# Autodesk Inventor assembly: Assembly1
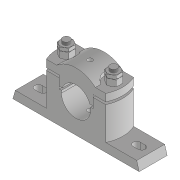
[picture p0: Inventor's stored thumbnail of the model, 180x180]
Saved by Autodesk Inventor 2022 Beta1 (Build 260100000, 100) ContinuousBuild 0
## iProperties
Created: 2021-03
Part Number: Assembly1
Document SubType Name: Assembly
Designer: ASUS Laptop
Author: ASUS Laptop
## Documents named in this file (7)
- D:\PROJECTS_2021\Resources\Tutorial Files\c09_Inv_2022_tut\c09_Inv_2021_tut\c09_Inv_tut_2021\c09_tut02_inv\Plummer Block\Assembly1.iam
- D:\PROJECTS_2021\Resources\Tutorial Files\c09_Inv_2022_tut\c09_Inv_2021_tut\c09_Inv_tut_2021\c09_tut02_inv\Plummer Block\Casting.ipt
- D:\PROJECTS_2021\Resources\Tutorial Files\c09_Inv_2022_tut\c09_Inv_2021_tut\c09_Inv_tut_2021\c09_tut02_inv\Plummer Block\Brasses.ipt
- D:\PROJECTS_2021\Resources\Tutorial Files\c09_Inv_2022_tut\c09_Inv_2021_tut\c09_Inv_tut_2021\c09_tut02_inv\Plummer Block\Cap.ipt
- D:\PROJECTS_2021\Resources\Tutorial Files\c09_Inv_2022_tut\c09_Inv_2021_tut\c09_Inv_tut_2021\c09_tut02_inv\Plummer Block\Bolt.ipt
- D:\PROJECTS_2021\Resources\Tutorial Files\c09_Inv_2022_tut\c09_Inv_2021_tut\c09_Inv_tut_2021\c09_tut02_inv\Plummer Block\Nut.ipt
- D:\PROJECTS_2021\Resources\Tutorial Files\c09_Inv_2022_tut\c09_Inv_2021_tut\c09_Inv_tut_2021\c09_tut02_inv\Plummer Block\locknut.ipt
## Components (9 placed, 6 different names)
1. Casting:1 — Mate:1, Mate:2, Insert:1, Insert:2, Angle:1, Angle:2
2. Brasses:1 — Mate:1, Mate:2, Mate:3, Mate:4
3. Cap:1 — Mate:3, Mate:4, Insert:3, Insert:5
4. Bolt:1 — Insert:2, Angle:1
5. Bolt:2 — Insert:1, Angle:2
6. Nut:1 — Insert:5, Insert:6
7. Nut:2 — Insert:3, Insert:4
8. locknut:1 — Insert:4
9. locknut:2 — Insert:6
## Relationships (12: Insert 6, Mate 4, Angle 2)
- Mate:1: Casting:1 ↔ Brasses:1
- Mate:2: Casting:1 ↔ Brasses:1
- Mate:3: Brasses:1 ↔ Cap:1
- Mate:4: Brasses:1 ↔ Cap:1
- Insert:1: Casting:1 ↔ Bolt:2
- Insert:2: Casting:1 ↔ Bolt:1
- Angle:1: Casting:1 ↔ Bolt:1
- Angle:2: Casting:1 ↔ Bolt:2
- Insert:3: Cap:1 ↔ Nut:2
- Insert:4: Nut:2 ↔ locknut:1
- Insert:5: Cap:1 ↔ Nut:1
- Insert:6: Nut:1 ↔ locknut:2
